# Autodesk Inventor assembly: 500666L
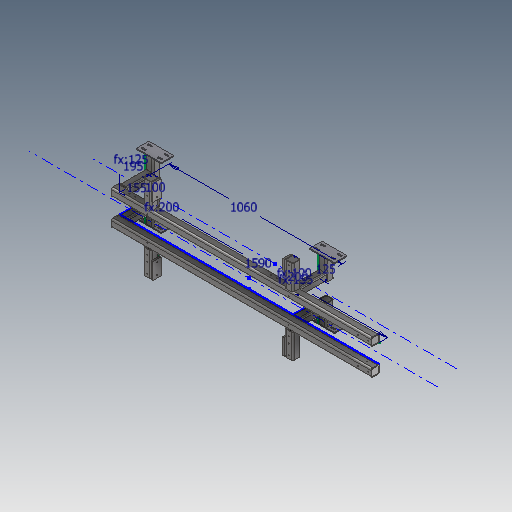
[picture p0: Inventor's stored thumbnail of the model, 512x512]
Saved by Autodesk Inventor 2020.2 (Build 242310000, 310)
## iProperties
_SolveAssemblyDoc: Frame Generator Solve Assembly
_Version: 15.0.0
Created: 2019-11
Part Number: 500666L
Document SubType Name: Assembly
Designer: lutzd
Mass: 36391.9 g
Surface Area: 18649.6 cm^2
Volume: 4636.56 cm^3
Density: 7.8489 g/cm^3
VLDS_Profile: Default Assembly
VLDS_TimeStamp: 2016-07-29
VLDS_FailCnt: 0
VLDS_AcceptCnt: 0
Dimensions: 281x514x1641,2 mm
Mass: 36,392 kg
DocNumber: 500666L.iam
Folder: 01 - Themengebiete\Simplification\01 - Packaging machine\Parts\
VDS_Category: 3D Komponenten
Author: lutzd
Revision Number: -
Title: 500666L
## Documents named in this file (4)
- D:\07 - DEMODATEN\OTX 2019 - Dataset - UPDATE - Dez2019\Designs\07-Packing machine\500666L.iam
- D:\07 - DEMODATEN\OTX 2019 - Dataset - UPDATE - Dez2019\Designs\07-Packing machine\Parts\ADSK-014410.ipt
- D:\07 - DEMODATEN\OTX 2019 - Dataset - UPDATE - Dez2019\Designs\07-Packing machine\500666L\Frame\ADSK-014411.iam
- D:\07 - DEMODATEN\OTX 2019 - Dataset - UPDATE - Dez2019\Designs\07-Packing machine\Parts\ADSK-011653.ipt
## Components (6 placed, 3 different names)
1. ADSK-014410:1
2. ADSK-014411:1 [sub-assembly] — Passend:1, Passend:2, Passend:3, Passend:4, Fluchtend:1, Fluchtend:2, Passend:5, Passend:6, Passend:7, Passend:8, Fluchtend:3, Fluchtend:4
3. ADSK-011653:1 — Passend:2, Passend:3, Fluchtend:2
4. ADSK-011653:2 — Passend:1, Passend:4, Fluchtend:1
5. ADSK-011653:3 — Passend:6, Passend:7, Fluchtend:4
6. ADSK-011653:4 — Passend:5, Passend:8, Fluchtend:3
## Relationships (12: Mate 8, Flush 4)
- Passend:1 [Mate]: ADSK-014411:1 ↔ ADSK-011653:2
- Passend:2 [Mate]: ADSK-014411:1 ↔ ADSK-011653:1
- Passend:3 [Mate]: ADSK-014411:1 ↔ ADSK-011653:1
- Passend:4 [Mate]: ADSK-014411:1 ↔ ADSK-011653:2
- Fluchtend:1 [Flush]: ADSK-014411:1 ↔ ADSK-011653:2
- Fluchtend:2 [Flush]: ADSK-014411:1 ↔ ADSK-011653:1
- Passend:5 [Mate]: ADSK-014411:1 ↔ ADSK-011653:4
- Passend:6 [Mate]: ADSK-014411:1 ↔ ADSK-011653:3
- Passend:7 [Mate]: ADSK-014411:1 ↔ ADSK-011653:3
- Passend:8 [Mate]: ADSK-014411:1 ↔ ADSK-011653:4
- Fluchtend:3 [Flush]: ADSK-014411:1 ↔ ADSK-011653:4
- Fluchtend:4 [Flush]: ADSK-014411:1 ↔ ADSK-011653:3
